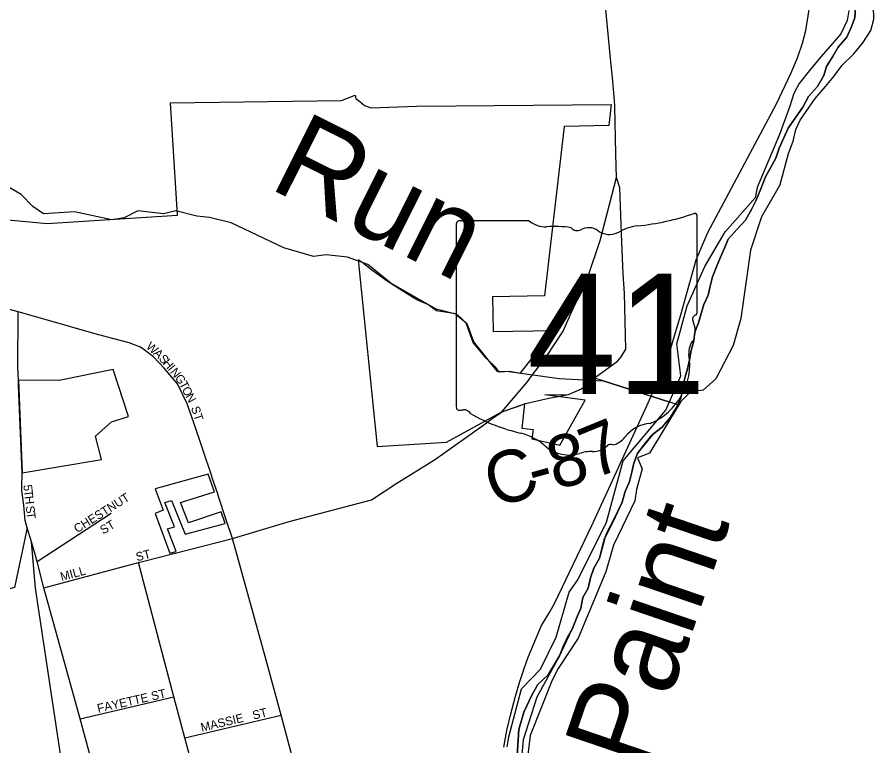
# Model space of a CAD drawing. Extents: x 1525783 to 1900577, y 218250 to 627376.
# Drawn here: x 1716711 to 1721660, y 495426 to 499637 of the extents above; entities that cross this region are included whole.
import ezdxf

# ---------------------------------------------------------------- set-up
doc = ezdxf.new("R2010")
doc.units = 0
for name, color, linetype in [('GM_X_Adjacent_County', 7, 'Continuous'), ('GM_X_City_Street', 7, 'Continuous'), ('GM_X_City_Street_Text', 7, 'Continuous'), ('GM_X_Corporation', 7, 'Continuous'), ('GM_X_County', 7, 'Continuous'), ('GM_X_County_Road', 7, 'Continuous'), ('GM_X_County_Road_Text', 7, 'Continuous'), ('GM_X_Major_River', 7, 'Continuous'), ('GM_X_Major_River_Text', 7, 'Continuous'), ('GM_X_Minor_River', 7, 'Continuous'), ('GM_X_Minor_River_Text', 7, 'Continuous'), ('GM_X_Rail_Line', 7, 'Continuous'), ('GM_X_State_Location', 7, 'Continuous'), ('GM_X_State_Route', 7, 'Continuous'), ('GM_X_State_Shield', 7, 'Continuous'), ('GM_X_Township', 7, 'Continuous'), ('GM_X_Township_Road', 7, 'Continuous')]:
    doc.layers.add(name, color=color, linetype=linetype)

msp = doc.modelspace()

# ---------------------------------------------------------------- linework, layer by layer
at = {"layer": 'GM_X_Adjacent_County'}
msp.add_lwpolyline([(1719591.8, 495253.1), (1719609.1, 495521.6), (1719638.6, 495620.1), (1719685.4, 495718.6), (1719719.9, 495780.2), (1719778.7, 495837.2), (1719813.7, 495894.6), (1719844.7, 495946.1), (1719865.7, 495999.8), (1719890.7, 496053.5), (1719919.6, 496105), (1719942.8, 496164.7), (1719967.8, 496222.4), (1719979, 496284.3), (1720010, 496337.8), (1720023.1, 496397.7), (1720042.1, 496453.4), (1720075.2, 496510.9), (1720088.2, 496562.8), (1720103.2, 496618.6), (1720126.2, 496672.3), (1720155.2, 496725.9), (1720182.2, 496781.5), (1720207.2, 496835.1), (1720224.4, 496896.9), (1720249.4, 496954.6), (1720262.4, 497008.4), (1720273.4, 497060.3), (1720294.5, 497116.1), (1720335.4, 497169.4), (1720380.4, 497222.6), (1720437.2, 497267.7), (1720486.3, 497324.9), (1720517.2, 497376.4), (1720544.2, 497430), (1720557.2, 497483.8), (1720566.4, 497545.8), (1720583.5, 497605.6), (1720594.5, 497657.5), (1720605.5, 497711.4), (1720620.5, 497767.2), (1720625.5, 497817.2), (1720646.5, 497871), (1720663.5, 497924.8), (1720678.4, 497976.6), (1720703.4, 498030.2), (1720714.4, 498082.1), (1720727.4, 498136), (1720750.5, 498193.7), (1720773.5, 498249.3), (1720798.5, 498303), (1720819.5, 498354.7), (1720870.5, 498411.8), (1720919.4, 498463), (1720954.7, 498528.5), (1720979.6, 498580.1), (1721006.8, 498645.7), (1721034.1, 498713.4), (1721063.1, 498766.9), (1721094.1, 498822.5), (1721113.2, 498880.2), (1721140.3, 498939.8), (1721166.2, 498994.7), (1721249.6, 499116.8), (1721283.2, 499178.1), (1721334.8, 499236.8), (1721370.5, 499300), (1721386, 499351.7), (1721425.6, 499412.8), (1721455, 499464.2), (1721504.6, 499521), (1721530.1, 499576.4), (1721549.6, 499634), (1721555.2, 499690)], dxfattribs=at)
at = {"layer": 'GM_X_City_Street'}
for points in [[(1717836.7, 496980.9), (1717835.5, 496984.5), (1717732.4, 497293.3), (1717693, 497401.8), (1717637.5, 497518.4), (1717561.1, 497609.2), (1717499.6, 497674), (1717452.6, 497709.7), (1717423.4, 497729.1), (1717358.6, 497755), (1717233.9, 497787.4), (1717141.6, 497813.3), (1716900.3, 497883), (1716717.5, 497934), (1716616.8, 497960.8), (1716393.5, 498039.6), (1716253.4, 498123.2), (1716118.1, 498196.6), (1715865.4, 498343.7)], [(1716720.1, 497506.7), (1716718.8, 497539), (1716715.8, 497613.8), (1716717.5, 497934)], [(1716763.7, 496707.7), (1716757.7, 496728.4), (1716749.4, 496816.3), (1716737.9, 496900.7), (1716738.3, 496919.4)], [(1717921.7, 496726.2), (1717921.4, 496727.2), (1717870.7, 496879)], [(1716827.9, 496491.2), (1717255.4, 496770.4)], [(1716866.2, 496339.4), (1717412.4, 496485.5), (1717442.6, 496493), (1717955.8, 496624.3)], [(1717198.7, 495122.1), (1717180.6, 495192.1), (1717075, 495582.1), (1716866.2, 496339.4), (1716827.9, 496491.2), (1716793.5, 496605.1)], [(1717771.2, 495128.7), (1717769.2, 495136.1), (1717714.2, 495344.3), (1717680.1, 495473.3), (1717617.4, 495710.3), (1717412.4, 496485.5)], [(1717075, 495582.1), (1717617.4, 495710.3)], [(1717680.1, 495473.3), (1718236.2, 495603)]]:
    msp.add_lwpolyline(points, dxfattribs=at)
at = {"layer": 'GM_X_Corporation'}
for points in [[(1716492, 498481.2), (1716884.3, 498444.4), (1717638.5, 498492.3), (1717597.2, 499141), (1718586.1, 499155.3), (1718664.2, 499185.3), (1718668.7, 499167.3), (1718691.2, 499149.3), (1718718.2, 499126.8), (1718754.2, 499113.3), (1719019.9, 499122.3), (1720142.2, 499133.2), (1720128.8, 499010.3), (1719872.2, 499005.8), (1719757.3, 498025.9), (1719457.3, 498021.1), (1719460.5, 497821.1), (1719810.5, 497826.7), (1719615.3, 497577.7), (1719556.8, 497589.4), (1719496.6, 497586.4), (1719476.1, 497613.1), (1719420.6, 497666.6), (1719346.3, 497757.8), (1719304.7, 497868.1), (1719257.4, 497908.6), (1719244.9, 497922.9), (1719133.5, 497940.7), (1719084, 497976.7), (1719020.9, 498003.8), (1718939.9, 498053.3), (1718849.8, 498111.8), (1718759.8, 498174.9), (1718710.2, 498215.4), (1718680.8, 498234.6), (1718791.8, 497156), (1719191, 497181.4), (1719511.4, 497355.8), (1719643, 497402.5), (1719626, 497262.8), (1719691.7, 497255), (1719685.2, 497199.6), (1719846.3, 497164.6), (1719991.8, 497424.5), (1719760.2, 497453.9), (1719897.3, 497456), (1719972.4, 497489.5), (1720047.5, 497552.6), (1720528.7, 497399.2), (1720486.8, 497325.8), (1720468.2, 497303.8), (1720430.8, 497262.6), (1720382.1, 497224), (1720294, 497115), (1720271.8, 497052.8), (1720249.5, 496954.8), (1720224.7, 496897.7), (1720204.8, 496830), (1720153.6, 496723), (1720106.2, 496625.6), (1720074.9, 496510.5), (1720042.2, 496453.5), (1720024.2, 496400.9), (1720010.2, 496339.1), (1719979, 496284.3), (1719968.2, 496224.3), (1719953.4, 496190.4), (1719913.6, 496094.3), (1719842.2, 495942), (1719713.9, 495707.5), (1719635.5, 495460.4), (1719615.9, 495249.8)], [(1716967.2, 495338.9), (1716816.6, 496336.5), (1716793.6, 496605.1), (1716770.1, 496685.5), (1716695.3, 496341.8), (1715618.2, 496052.8), (1713798.3, 495575.7), (1713951.6, 494960.5)]]:
    msp.add_lwpolyline(points, dxfattribs=at)
for points in [[(1716718.8, 497539), (1716740.1, 497004.4), (1717199.6, 497081.6), (1717163.6, 497216.1), (1717256.9, 497299.3), (1717355.5, 497328.9), (1717265.5, 497601.5), (1716954.4, 497536.6)], [(1717508.4, 496912.1), (1717555.4, 496788), (1717554.4, 496787.4), (1717508.9, 496769.1), (1717593.5, 496539.1), (1717629.9, 496549.6), (1717580.8, 496680.3), (1717619.9, 496692.7), (1717564.9, 496832.2), (1717604, 496844.6), (1717682.5, 496648.8), (1717913.1, 496711.7), (1717889.8, 496777.7), (1717700.9, 496714.2), (1717655.5, 496833.2), (1717852.2, 496893.9), (1717814.3, 496996.7)]]:
    msp.add_lwpolyline(points, close=True, dxfattribs=at)
at = {"layer": 'GM_X_County'}
msp.add_lwpolyline([(1721555.2, 499690), (1721549.6, 499634), (1721530.1, 499576.4), (1721504.6, 499521), (1721455, 499464.2), (1721425.6, 499412.8), (1721386, 499351.7), (1721370.5, 499300), (1721334.8, 499236.8), (1721283.2, 499178.1), (1721249.6, 499116.8), (1721166.2, 498994.7), (1721140.3, 498939.8), (1721113.2, 498880.2), (1721094.1, 498822.5), (1721063.1, 498766.9), (1721034.1, 498713.4), (1721006.8, 498645.7), (1720979.6, 498580.1), (1720954.7, 498528.5), (1720919.4, 498463), (1720870.5, 498411.8), (1720819.5, 498354.7), (1720798.5, 498303), (1720773.5, 498249.3), (1720750.5, 498193.7), (1720727.4, 498136), (1720714.4, 498082.1), (1720703.4, 498030.2), (1720678.4, 497976.6), (1720663.5, 497924.8), (1720646.5, 497871), (1720625.5, 497817.2), (1720620.5, 497767.2), (1720605.5, 497711.4), (1720594.5, 497657.5), (1720583.5, 497605.6), (1720566.4, 497545.8), (1720557.2, 497483.8), (1720544.2, 497430), (1720517.2, 497376.4), (1720486.3, 497324.9), (1720437.2, 497267.7), (1720380.4, 497222.6), (1720335.4, 497169.4), (1720294.5, 497116.1), (1720273.4, 497060.3), (1720262.4, 497008.4), (1720249.4, 496954.6), (1720224.4, 496896.9), (1720207.2, 496835.1), (1720182.2, 496781.5), (1720155.2, 496725.9), (1720126.2, 496672.3), (1720103.2, 496618.6), (1720088.2, 496562.8), (1720075.2, 496510.9), (1720042.1, 496453.4), (1720023.1, 496397.7), (1720010, 496337.8), (1719979, 496284.3), (1719967.8, 496222.4), (1719942.8, 496164.7), (1719919.6, 496105), (1719890.7, 496053.5), (1719865.7, 495999.8), (1719844.7, 495946.1), (1719813.7, 495894.6), (1719778.7, 495837.2), (1719719.9, 495780.2), (1719685.4, 495718.6), (1719638.6, 495620.1), (1719609.1, 495521.6), (1719591.8, 495253.1)], dxfattribs=at)
at = {"layer": 'GM_X_County_Road'}
for points in [[(1720008, 497519.4), (1720047.4, 497552.5), (1720107.8, 497596.8), (1720180.2, 497649.1), (1720200.3, 497673.3), (1720228.3, 497718.5), (1720219, 498039.4), (1720212.1, 498154.3), (1720205.2, 498335.5), (1720193.6, 498650.6), (1720172.9, 498710.6)], [(1719834.9, 497444.8), (1719897.3, 497456), (1719972.4, 497489.5), (1720008, 497519.4)], [(1719647.4, 497403.5), (1719783.7, 497435.6), (1719834.9, 497444.8)], [(1719511.5, 497355.8), (1719601.4, 497387.8), (1719643, 497402.5), (1719647.4, 497403.5)], [(1717870.7, 496879), (1717869.9, 496881.6), (1717836.7, 496980.9)], [(1717955.8, 496624.3), (1717921.7, 496726.2)]]:
    msp.add_lwpolyline(points, dxfattribs=at)
at = {"layer": 'GM_X_Major_River'}
for points in [[(1721119.6, 498669.4), (1721166.6, 498848.7), (1721193.5, 498920.5), (1721210.4, 498988.5), (1721235, 499042.3), (1721320.6, 499167.5), (1721381.5, 499236.9), (1721428.2, 499294.5), (1721477, 499360), (1721543.9, 499425.4), (1721596.6, 499488.9), (1721643.5, 499560.5), (1721660.3, 499624.4), (1721657.3, 499700.6)], [(1721514.9, 499676.2), (1721506.2, 499618.2), (1721469.2, 499540.5), (1721420.5, 499485), (1721355.6, 499409.6), (1721296.7, 499338.1), (1721229.6, 499252.7), (1721198.9, 499195), (1721174, 499123.1), (1721114.3, 498959.5)], [(1721114.3, 498959.5), (1720986.6, 498652.1), (1720973.8, 498592.1), (1720800.8, 498397.2)], [(1721119.6, 498669.4), (1721010.4, 498482.6), (1720947.2, 498291.1), (1720892.8, 497895), (1720848.2, 497739.3), (1720746.9, 497546.3), (1720673.8, 497481.3), (1720601.5, 497472.4), (1720544.5, 497415.1), (1720363.4, 497117.2), (1720294.9, 497090.1), (1720321.9, 497027.6), (1720290, 496907.8), (1720278.9, 496841.8), (1720156.6, 496585), (1720112, 496431.3), (1719951.6, 496048.8), (1719836.6, 495872.2), (1719801.5, 495806.5), (1719674.1, 495485.7), (1719639.4, 495197.5)], [(1719542.4, 495421.1), (1719551.2, 495479.1), (1719625.3, 495754.8), (1719735.2, 495869.5), (1719826, 496054.7), (1719899.8, 496314.3), (1719950.9, 496385.8), (1720116, 496718.3), (1720211.3, 497073.9), (1720457.9, 497365.2), (1720544.9, 497564.5), (1720521.5, 497749.2), (1720582.8, 497968.9), (1720684.3, 498196.1), (1720800.8, 498397.2)]]:
    msp.add_lwpolyline(points, dxfattribs=at)
at = {"layer": 'GM_X_Minor_River'}
msp.add_lwpolyline([(1720478.1, 497411.6), (1720097.8, 497532.6), (1719841.7, 497546.2), (1719554, 497588.3), (1719485.9, 497589.2), (1719350.2, 497761.5), (1719311.7, 497864.3), (1719252.4, 497919.2), (1719132.7, 497949), (1718870.5, 498099), (1718737.9, 498207.1), (1718620.4, 498250.8), (1718496.4, 498262.6), (1718424.2, 498253.5), (1718252.7, 498304.1), (1717948.4, 498448.6), (1717822.7, 498478.5), (1717748.7, 498487.5), (1717629, 498517.2), (1717556.7, 498500.2), (1717408.8, 498518.3), (1717330.1, 498477.3), (1717257.8, 498466.3), (1717042.2, 498511.3), (1716863.8, 498499.8), (1716802.4, 498542.8), (1716735.3, 498611.9), (1716604.2, 498687.9)], dxfattribs=at)
at = {"layer": 'GM_X_Rail_Line'}
msp.add_lwpolyline([(1719522.1, 495418.6), (1719540.5, 495515.7), (1719560.5, 495603.5), (1719590.5, 495712.9), (1719614, 495791.4), (1719638.6, 495868.3), (1719664.2, 495939.2), (1719740.9, 496120.9), (1719789.5, 496200.3), (1719817.7, 496252.8), (1720030.9, 496699.6), (1720349.8, 497390.5), (1720468.6, 497660.2), (1720545.4, 497916.1), (1720633.3, 498235.6), (1720701.5, 498392.5), (1721097.2, 499136.5), (1721181.5, 499311), (1721219.2, 499402.2), (1721248.1, 499487.5), (1721267.1, 499559.7), (1721287.4, 499681.8)], dxfattribs=at)
at = {"layer": 'GM_X_State_Route'}
for points in [[(1720139.4, 499398.6), (1720078.3, 500046.7), (1719964, 500964.3), (1719843.5, 501898.9), (1719807.9, 502184.9), (1719641.5, 502390.4), (1719367.8, 502873.4)], [(1720159.4, 499176.4), (1720149.8, 499288.4), (1720139.4, 499398.6)], [(1720163.8, 499120.8), (1720163.7, 499126.8), (1720159.4, 499176.4)], [(1719870.8, 497835.7), (1719914.7, 497932), (1720009, 498134.1), (1720079.4, 498345.9), (1720172.9, 498710.6), (1720170.6, 498846.9), (1720163.8, 499120.8)], [(1719681.4, 497560.3), (1719768.6, 497675.9), (1719865.2, 497823.4), (1719870.8, 497835.7)], [(1719500.8, 497348.4), (1719511.5, 497355.8), (1719657.4, 497528.4), (1719681.4, 497560.3)], [(1719183, 497121.6), (1719408, 497281.7), (1719455.6, 497317.1), (1719500.8, 497348.4)], [(1717955.8, 496624.3), (1718283.8, 496723.1), (1718759.1, 496847.7), (1718904.4, 496943.8), (1719122.5, 497078.5), (1719183, 497121.6)], [(1718311.6, 495325), (1718306.4, 495344.1), (1718236.2, 495603), (1718144, 495942.6), (1717955.8, 496624.3)]]:
    msp.add_lwpolyline(points, dxfattribs=at)
at = {"layer": 'GM_X_State_Shield'}
for p, q in [((1719669.8, 498459.2), (1719262.1, 498459.2)), ((1720640.6, 497932.6), (1720640.6, 498485.4)), ((1719248.4, 498441), (1719248.4, 497384.4)), ((1720640.5, 497932.8), (1720640.6, 497932.6))]:
    msp.add_line(p, q, dxfattribs=at)
for centre, radius, start, end in [((1720144.7, 499899.7), 1476.4, 275.8445, 288.9065), ((1720625.1, 498487.6), 15.5, 351.8621, 97.738), ((1719264.4, 498443.2), 16.1, 98.1301, 188.1301), ((1719766.9, 498581.8), 156.4, 231.6195, 271.1119), ((1719818.8, 497866), 561.6, 80.4867, 94.9883), ((1719946.3, 498448.7), 45.1, 219.7921, 297.1024), ((1720012.5, 498326.6), 93.8, 54.4667, 119.1411), ((1720133.7, 498494.1), 112.9, 233.8562, 294.8282), ((1720333, 498136.4), 297, 97.3462, 120.7689), ((1720637, 497892), 24, 107.944, 210.337), ((1720624.1, 497930.5), 16.6, 289.6038, 7.7341), ((1720484.4, 497822.2), 144, 340.033, 23.6496), ((1720696.1, 497701.3), 104.8, 136.8065, 186.9296), ((1720227.4, 497631), 369.3, 292.3089, 8.9858), ((1719264.5, 497382), 16.3, 171.9584, 258.3066), ((1719267, 497490.1), 124.2, 267.339, 280.6039), ((1719292.4, 497323.4), 44.8, 29.7484, 93.2717), ((1719857.7, 498272.7), 1066.1, 240.4129, 257.1985), ((1720383.1, 497087.7), 202.2, 94.4031, 142.5768), ((1719539.8, 496909.7), 333.6, 47.1842, 75.836), ((1720140.4, 497136.7), 31.8, 65.7517, 132.6484), ((1720126.8, 497281.9), 119.3, 282.8732, 323.2771), ((1719900.6, 497318.2), 211.7, 230.7004, 286.2918), ((1720022.9, 496952.8), 173.9, 85.6951, 111.2099), ((1720038.4, 497239), 112.8, 268.777, 315.5493)]:
    msp.add_arc(centre, radius, start, end, dxfattribs=at)
at = {"layer": 'GM_X_Township'}
msp.add_lwpolyline([(1721555.2, 499690), (1721549.6, 499634), (1721530.1, 499576.4), (1721504.6, 499521), (1721455, 499464.2), (1721425.6, 499412.8), (1721386, 499351.7), (1721370.5, 499300), (1721334.8, 499236.8), (1721283.2, 499178.1), (1721249.6, 499116.8), (1721166.2, 498994.7), (1721140.3, 498939.8), (1721113.2, 498880.2), (1721094.1, 498822.5), (1721063.1, 498766.9), (1721034.1, 498713.4), (1721006.8, 498645.7), (1720979.6, 498580.1), (1720954.7, 498528.5), (1720919.4, 498463), (1720870.5, 498411.8), (1720819.5, 498354.7), (1720798.5, 498303), (1720773.5, 498249.3), (1720750.5, 498193.7), (1720727.4, 498136), (1720714.4, 498082.1), (1720703.4, 498030.2), (1720678.4, 497976.6), (1720663.5, 497924.8), (1720646.5, 497871), (1720625.5, 497817.2), (1720620.5, 497767.2), (1720605.5, 497711.4), (1720594.5, 497657.5), (1720583.5, 497605.6), (1720566.4, 497545.8), (1720557.2, 497483.8), (1720544.2, 497430), (1720517.2, 497376.4), (1720486.3, 497324.9), (1720437.2, 497267.7), (1720380.4, 497222.6), (1720335.4, 497169.4), (1720294.5, 497116.1), (1720273.4, 497060.3), (1720262.4, 497008.4), (1720249.4, 496954.6), (1720224.4, 496896.9), (1720207.2, 496835.1), (1720182.2, 496781.5), (1720155.2, 496725.9), (1720126.2, 496672.3), (1720103.2, 496618.6), (1720088.2, 496562.8), (1720075.2, 496510.9), (1720042.1, 496453.4), (1720023.1, 496397.7), (1720010, 496337.8), (1719979, 496284.3), (1719967.8, 496222.4), (1719942.8, 496164.7), (1719919.6, 496105), (1719890.7, 496053.5), (1719865.7, 495999.8), (1719844.7, 495946.1), (1719813.7, 495894.6), (1719778.7, 495837.2), (1719719.9, 495780.2), (1719685.4, 495718.6), (1719638.6, 495620.1), (1719609.1, 495521.6), (1719591.8, 495253.1)], dxfattribs=at)
at = {"layer": 'GM_X_Township_Road'}
for points in [[(1716738.3, 496919.4), (1716740.1, 497004.4), (1716720.1, 497506.7)], [(1716793.5, 496605.1), (1716770.1, 496685.6), (1716763.7, 496707.7)]]:
    msp.add_lwpolyline(points, dxfattribs=at)

# ---------------------------------------------------------------- texts
at = {"layer": 'GM_X_City_Street_Text'}
for s, rotation, p in [('W', 319.7962, (1717452.2, 497727.1)), ('A', 315.541, (1717495.1, 497690.8)), ('S', 313.0104, (1717526.1, 497660.4)), ('H', 311.3504, (1717549.9, 497634.9)), ('I', 309.1787, (1717578.6, 497602.3)), ('N', 308.8203, (1717592.5, 497585.3)), ('G', 306.0306, (1717619.7, 497551.5)), ('T', 298.3729, (1717644.6, 497517.4)), ('O', 296.9169, (1717661.2, 497486.8)), ('N', 298.9488, (1717682, 497445.8)), ('ST', 288.4306, (1717714.7, 497379.6)), ('5', 276.4436, (1716747.2, 496933.1)), ('T', 276.4337, (1716750.6, 496902.5)), ('H', 276.4416, (1716754.6, 496867.5)), ('CHESTNUT', 32.167, (1717058.4, 496654.2)), ('S', 276.4472, (1716761, 496810.7)), ('T', 277.3738, (1716765, 496774.8)), ('ST', 31.6, (1717209.2, 496646.9)), ('ST', 14.0266, (1717404.3, 496492.5)), ('MILL', 15.259, (1716968.5, 496378)), ('FAYETTE ST', 12.8343, (1717180.1, 495617)), ('ST', 14.0266, (1718077.5, 495577.3)), ('MASSIE', 13.4971, (1717778.4, 495506.9))]:
    msp.add_text(s, height=50, rotation=rotation, dxfattribs=at).set_placement(p)
at = {"layer": 'GM_X_County_Road_Text'}
for s, rotation, p in [('7', 22.2633, (1720039.5, 496964.6)), ('8', 13.7385, (1719815.1, 496906)), ('C', 19.3305, (1719474.1, 496794.5)), ('-', 15.5443, (1719699.9, 496873.9))]:
    msp.add_text(s, height=300, rotation=rotation, dxfattribs=at).set_placement(p)
at = {"layer": 'GM_X_Major_River_Text'}
msp.add_text('Paint', height=500.01, rotation=71.116, dxfattribs=at).set_placement((1720336.1, 495275))
at = {"layer": 'GM_X_Minor_River_Text'}
msp.add_text('Run', height=499.99, rotation=333.4264, dxfattribs=at).set_placement((1718156.5, 498652.4))
at = {"layer": 'GM_X_State_Location'}
for s in ['s', 'r']:
    msp.add_text(s, height=1, dxfattribs=at).set_placement((1719928.8, 497842.4))
msp.add_text('41', height=1, rotation=0, dxfattribs=at).set_placement((1719677, 497769.7))
at = {"layer": 'GM_X_State_Shield'}
msp.add_text('41', height=696.1, dxfattribs=at).set_placement((1719655.7, 497458.9))

doc.saveas('drawing.dxf')
